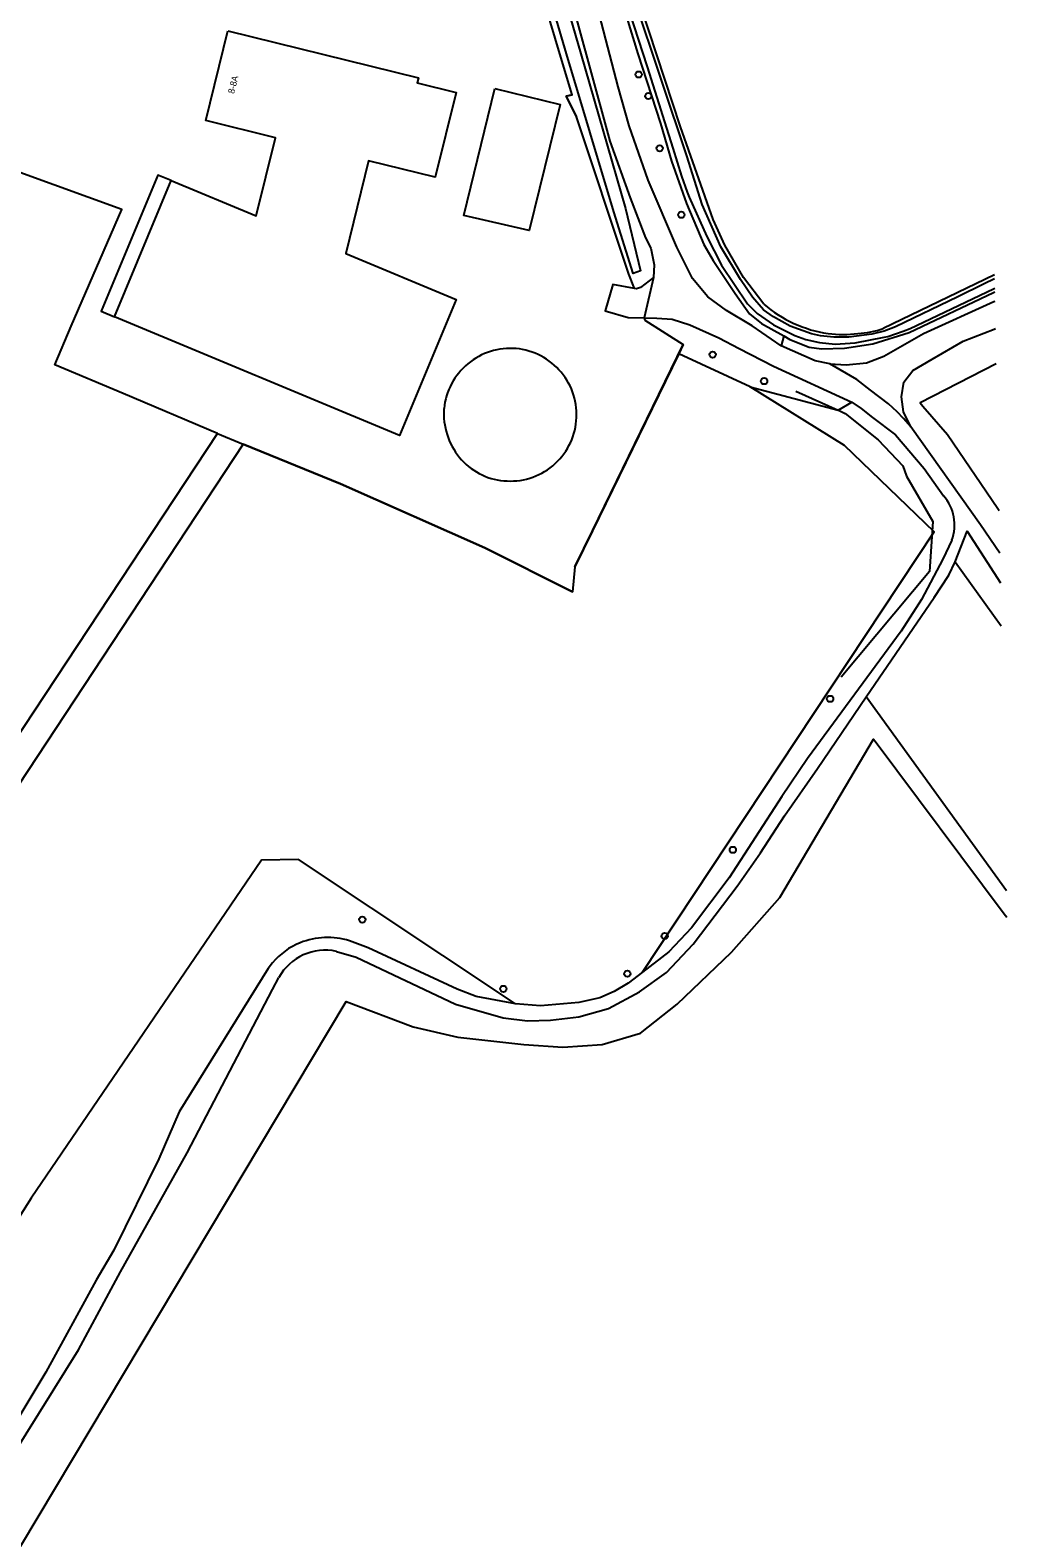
# Model space of a CAD drawing. Extents: x 163863 to 164644, y 379566 to 382155.
# Drawn here: x 164462.3 to 164614.2, y 381019.3 to 381253.7 of the extents above; entities that cross this region are included whole.
import ezdxf

# ---------------------------------------------------------------- set-up
doc = ezdxf.new("R2010")
doc.units = 0
for name, color, linetype in [('IMGEO_Berm_groen', 7, 'Continuous'), ('IMGEO_Boom', 7, 'Continuous'), ('IMGEO_Gemengd_bos', 7, 'Continuous'), ('IMGEO_Grasland_agrarisch', 7, 'Continuous'), ('IMGEO_Grasland_overig', 7, 'Continuous'), ('IMGEO_Groenvoorziening', 7, 'Continuous'), ('IMGEO_Hek', 7, 'Continuous'), ('IMGEO_Loofbos', 7, 'Continuous'), ('IMGEO_Open_loods', 7, 'Continuous'), ('IMGEO_Pand', 7, 'Continuous'), ('IMGEO_Pand_nummerreeks', 7, 'Continuous'), ('IMGEO_Pand_overbouw', 7, 'Continuous'), ('IMGEO_Rijbaan_lokaal_onverhard', 7, 'Continuous'), ('IMGEO_Rijbaan_lokaal_open', 7, 'Continuous'), ('IMGEO_Sloot', 7, 'Continuous'), ('IMGEO_Waterloop', 7, 'Continuous')]:
    doc.layers.add(name, color=color, linetype=linetype)

msp = doc.modelspace()

# ---------------------------------------------------------------- linework, layer by layer
at = {"layer": 'IMGEO_Berm_groen'}
for points in [[(164579.48, 381206.15), (164580.44, 381205.6), (164583.43, 381204.4), (164585.35, 381204.15), (164588.95, 381204.24), (164593.32, 381204.91), (164599.01, 381206.67), (164612.12, 381212.9), (164612.31, 381212.99)], [(164579.48, 381206.15), (164579.11, 381204.6)], [(164612.52, 381201.83), (164600.71, 381195.76), (164601.11, 381195.25), (164604.93, 381190.83), (164612.77, 381179.3), (164612.96, 381179.03)]]:
    msp.add_lwpolyline(points, dxfattribs=at)
at = {"layer": 'IMGEO_Boom'}
for centre in [(164556.92, 381246.81), (164558.42, 381243.45), (164560.21, 381235.34), (164563.56, 381224.99), (164568.43, 381203.25), (164576.44, 381199.13), (164586.7, 381149.73), (164571.57, 381126.25), (164513.95, 381115.39), (164560.97, 381112.84), (164555.18, 381106.99), (164535.89, 381104.63)]:
    msp.add_circle(centre, 0.489, dxfattribs=at)
at = {"layer": 'IMGEO_Gemengd_bos'}
for points in [[(164557.53, 381107.22), (164602.9, 381175.67), (164588.92, 381189.1), (164574.27, 381198.23)], [(164574.27, 381198.23), (164587.94, 381194.61), (164590.09, 381195.84)]]:
    msp.add_lwpolyline(points, dxfattribs=at)
at = {"layer": 'IMGEO_Grasland_agrarisch'}
for points in [[(164576.41, 381211.1), (164573.23, 381215.26), (164570.32, 381220.27), (164568.53, 381224.27), (164563.46, 381238.67), (164557.34, 381257.3), (164556.93, 381259.1), (164557.37, 381263.39), (164552.4, 381279.61), (164551.54, 381283.27), (164550.85, 381284.34), (164548.58, 381287.22), (164544.33, 381298.3), (164538.21, 381318.01), (164536.75, 381321.62), (164536.3, 381322.47)], [(164491.42, 381190.96), (164476.78, 381197.2), (164466.17, 381201.68), (164468.67, 381207.69), (164476.57, 381225.79), (164455.37, 381233.49), (164449.22, 381234.75), (164447.64, 381227.22), (164435.91, 381232.23), (164414.92, 381240.8), (164405.79, 381228.47)], [(164612.26, 381215.65), (164594.95, 381207.29)], [(164563.17, 381203.39), (164549.74, 381175.85), (164547, 381170.23), (164546.62, 381166.36), (164532.99, 381173.22), (164510.56, 381183.16), (164495.42, 381189.33)], [(164574.27, 381198.23), (164563.17, 381203.39)]]:
    msp.add_lwpolyline(points, dxfattribs=at)
for centre, radius, start, end in [((164589.43, 381226.31), 20.03, 229.4578, 261.2234), ((164588.66, 381224.46), 18.08, 262.7499, 277.4727), ((164590.23, 381221.16), 14.65, 273.04, 288.814)]:
    msp.add_arc(centre, radius, start, end, dxfattribs=at)
at = {"layer": 'IMGEO_Grasland_overig'}
for points in [[(164495.42, 381189.33), (164397.81, 381041.2), (164394.38, 381043.92), (164491.42, 381190.96)], [(164491.42, 381190.96), (164495.42, 381189.33)]]:
    msp.add_lwpolyline(points, dxfattribs=at)
at = {"layer": 'IMGEO_Groenvoorziening'}
for points in [[(164536.3, 381322.47), (164536.11, 381322.4), (164534.55, 381321.89), (164534.29, 381321.38), (164536.91, 381312.6), (164539.75, 381303.88), (164542.82, 381293.93), (164545.36, 381286.71), (164546.33, 381285.83), (164548.13, 381283.64), (164548.81, 381282.59), (164554.8, 381263.71), (164554.09, 381259.85), (164554.07, 381259.03), (164556.78, 381250.03), (164560.31, 381239.18), (164562.03, 381233.31), (164564.38, 381226.73), (164567.04, 381220.38), (164568.5, 381217.9), (164571.91, 381212.76), (164574.18, 381209.58), (164576.04, 381208.08), (164579.48, 381206.15)], [(164556.3, 381213.51), (164555.39, 381215.78), (164555.19, 381216.36), (164547.24, 381240.23), (164545.64, 381243.44), (164546.57, 381243.66), (164544.69, 381250), (164540.48, 381264.15), (164540.22, 381265.04), (164529.13, 381268.21), (164519.66, 381272.56), (164519.13, 381272.75)], [(164557.76, 381208.98), (164557.87, 381208.62), (164563.87, 381204.82), (164563.17, 381203.39)]]:
    msp.add_lwpolyline(points, dxfattribs=at)
at = {"layer": 'IMGEO_Hek'}
for points in [[(164546.57, 381243.66), (164545.64, 381243.44), (164547.24, 381240.23)], [(164468.67, 381207.69), (164476.57, 381225.79), (164455.37, 381233.49), (164449.22, 381234.75)], [(164491.42, 381190.96), (164476.78, 381197.2), (164466.17, 381201.68), (164468.67, 381207.69)], [(164547, 381170.23), (164549.74, 381175.85), (164563.87, 381204.82)], [(164581.36, 381197.59), (164587.94, 381194.61)], [(164587.94, 381194.61), (164588.1, 381194.54)], [(164588.1, 381194.54), (164589.05, 381194.1), (164594.17, 381190.01), (164597.98, 381185.97), (164598.57, 381184.37), (164602.69, 381177.28), (164602.15, 381169.55), (164588.41, 381153.12)], [(164495.42, 381189.33), (164397.81, 381041.2), (164394.38, 381043.92), (164491.42, 381190.96)], [(164491.42, 381190.96), (164495.42, 381189.33)], [(164495.42, 381189.33), (164510.56, 381183.16), (164532.99, 381173.22), (164546.62, 381166.36)]]:
    msp.add_lwpolyline(points, dxfattribs=at)
at = {"layer": 'IMGEO_Loofbos'}
for points in [[(164606.14, 381171.03), (164613.31, 381161.07)], [(164614.1, 381119.89), (164592.33, 381150.04)], [(164459.78, 380894.18), (164434.24, 380899.21), (164433.15, 380965.61), (164434.34, 380973.7), (164511.44, 381102.66), (164521.89, 381098.72), (164528.79, 381097.14), (164539.05, 381095.96), (164545.16, 381095.56), (164551.27, 381095.96), (164557.19, 381097.73), (164562.91, 381102.27), (164571.39, 381110.35), (164578.88, 381118.83), (164593.47, 381143.48), (164593.71, 381143.13), (164613.76, 381116.31), (164614.18, 381115.76)], [(164537.77, 381102.28), (164504.04, 381124.74), (164498.31, 381124.65), (164462.45, 381072.06), (164450.08, 381052.56), (164433.46, 381023.94), (164416.65, 380993.03), (164417.52, 380979.9)]]:
    msp.add_lwpolyline(points, dxfattribs=at)
at = {"layer": 'IMGEO_Open_loods'}
for centre, radius, start, end in [((164537.02, 381193.77), 10.45, 85.2742, 129.4704), ((164536.91, 381193.84), 10.39, 39.9242, 84.6782), ((164537.04, 381193.81), 10.43, 129.7074, 174.2176), ((164537.07, 381193.95), 10.2, 354.472, 40.0119), ((164537.55, 381194.13), 10.92, 176.1353, 218.8855), ((164537, 381193.87), 10.27, 309.7584, 354.9208), ((164536.78, 381193.59), 9.98, 219.2706, 265.2458), ((164537, 381193.79), 10.2, 264.0995, 310.0286)]:
    msp.add_arc(centre, radius, start, end, dxfattribs=at)
at = {"layer": 'IMGEO_Pand'}
for points in [[(164493.07, 381253.59), (164522.69, 381246.3), (164522.5, 381245.5), (164528.55, 381244.02), (164525.29, 381230.84), (164514.94, 381233.36), (164511.38, 381218.98), (164528.53, 381211.84), (164519.74, 381190.67), (164475.41, 381209.15), (164484.22, 381230.3), (164497.43, 381224.83), (164500.46, 381236.94), (164489.62, 381239.63), (164493.07, 381253.59)], [(164534.59, 381244.64), (164544.74, 381242.15), (164539.92, 381222.53), (164529.75, 381224.89), (164534.59, 381244.64)]]:
    msp.add_lwpolyline(points, dxfattribs=at)
at = {"layer": 'IMGEO_Pand_overbouw'}
msp.add_lwpolyline([(164484.22, 381230.3), (164482.19, 381231.14), (164473.38, 381210), (164475.41, 381209.15)], close=True, dxfattribs=at)
at = {"layer": 'IMGEO_Rijbaan_lokaal_onverhard'}
for points in [[(164474.21, 381290.55), (164483.96, 381287.46), (164498.67, 381282.49), (164519.5, 381276.01), (164529.34, 381273.18), (164538.66, 381270.43), (164541.43, 381268.75), (164543.02, 381266.93), (164544.34, 381264.96), (164545.66, 381261.33), (164549.08, 381248.8), (164552.47, 381236.46), (164555.63, 381227.65), (164557.99, 381221.41), (164558.81, 381219.82), (164559.36, 381217.23), (164559.22, 381215.24)], [(164579.11, 381204.6), (164574.56, 381207.73), (164570.59, 381210.11), (164567.68, 381212.22), (164565.32, 381215.07), (164562.87, 381219.96), (164558.43, 381230.39), (164555.47, 381238.84), (164553.72, 381244.89), (164550.85, 381256.01), (164547.6, 381267.91), (164544.02, 381275.23)], [(164586.65, 381201.83), (164589.18, 381201.68), (164592.36, 381201.97), (164595.03, 381203.03), (164601.2, 381206.54), (164612.15, 381211.51), (164612.34, 381211.58)], [(164557.76, 381208.98), (164559.78, 381208.94), (164562.14, 381208.75), (164564.89, 381207.88), (164569.39, 381205.84), (164572.58, 381204.2), (164577.91, 381201.43), (164590.09, 381195.84)], [(164599.24, 381192.03), (164598.11, 381194.37), (164597.81, 381196.68), (164598.14, 381198.98), (164599.56, 381200.8), (164602.57, 381202.55), (164607.37, 381205.34), (164612.23, 381207.21), (164612.42, 381207.3)], [(164586.65, 381201.83), (164584.36, 381202.3), (164579.11, 381204.6)], [(164599.24, 381192.03), (164598.13, 381193.31), (164597.11, 381194.38), (164595.79, 381195.61), (164593, 381197.74), (164590.86, 381199.36), (164586.65, 381201.83)], [(164590.09, 381195.84), (164591.51, 381194.86), (164593.3, 381193.47), (164596.85, 381190.77), (164601.31, 381185.54), (164604.35, 381181.3)], [(164613.09, 381172.4), (164610.08, 381176.78), (164599.24, 381192.03)], [(164606.14, 381171.03), (164607.99, 381175.81), (164613.18, 381167.75)], [(164605.64, 381174.38), (164604.2, 381171.47), (164600.92, 381165.15), (164597.75, 381160.27), (164583.18, 381140.44), (164579.18, 381134.54), (164571.02, 381121.89), (164565.12, 381114.11), (164561.61, 381110.39), (164557.53, 381107.22)], [(164592.33, 381150.04), (164602.88, 381165.5), (164605.16, 381168.97), (164606.14, 381171.03)], [(164509.94, 381110.46), (164513, 381109.56), (164528.45, 381102.23), (164535.88, 381100.11), (164539.67, 381099.67), (164543.21, 381099.75), (164547.64, 381100.28), (164552.22, 381101.59), (164557.08, 381104.16), (164561.26, 381107.19), (164565.4, 381111.59), (164572.27, 381120.6), (164575.89, 381125.77), (164579.6, 381131.54), (164584.73, 381138.89), (164592.33, 381150.04)], [(164537.77, 381102.28), (164531.66, 381103.46), (164528.71, 381104.56), (164514.89, 381111.01), (164511.96, 381112.11)], [(164500, 381108.67), (164499.33, 381107.79), (164485.48, 381085.49), (164482.32, 381078.21), (164475.33, 381063.99), (164472.56, 381059.31), (164464.73, 381045.03), (164457.76, 381033.36), (164451.17, 381024.3), (164449.47, 381021.73), (164448.22, 381019.51), (164443.56, 381010.28), (164437.71, 381000), (164430.52, 380987.39), (164427.27, 380980.74)], [(164557.53, 381107.22), (164555.31, 381105.49), (164553.14, 381104.2), (164550.89, 381103.22), (164547.61, 381102.5), (164541.67, 381102), (164537.77, 381102.28)], [(164430.23, 380982.04), (164433.13, 380988.18), (164439.99, 381000), (164451.52, 381019.23), (164469.81, 381048.48), (164476.37, 381060.64), (164486.72, 381079.14), (164500, 381104.54), (164500.97, 381106.4)]]:
    msp.add_lwpolyline(points, dxfattribs=at)
for centre, radius, start, end in [((164599.17, 381176.75), 6.89, 339.9252, 41.3342), ((164508.34, 381101.72), 10.86, 111.8485, 140.1745), ((164508.57, 381101.12), 11.5, 72.8645, 111.8003), ((164508.22, 381102.31), 8.33, 78.1113, 150.583)]:
    msp.add_arc(centre, radius, start, end, dxfattribs=at)
at = {"layer": 'IMGEO_Rijbaan_lokaal_open'}
for points in [[(164559.22, 381215.24), (164557.24, 381213.71), (164556.58, 381213.46), (164556.3, 381213.51)], [(164559.22, 381215.24), (164557.76, 381208.98)], [(164556.3, 381213.51), (164552.9, 381214.15), (164551.74, 381210.06), (164555.31, 381209.02), (164557.76, 381208.98)]]:
    msp.add_lwpolyline(points, dxfattribs=at)
at = {"layer": 'IMGEO_Sloot'}
for points in [[(164554.85, 381258.56), (164558.24, 381248), (164560.95, 381239.43), (164562.23, 381235.35), (164563.59, 381231.01), (164564.48, 381228.53), (164564.76, 381227.74), (164567.53, 381221.61), (164569.82, 381217.16), (164573.86, 381211.15), (164575.36, 381209.65), (164577.88, 381207.87), (164581.23, 381206.22), (164582.94, 381205.6), (164585.04, 381205.16), (164587.47, 381204.89), (164590.58, 381205.08), (164595.1, 381205.99), (164595.65, 381206.09), (164598.04, 381206.92), (164599.14, 381207.33), (164612.11, 381213.48), (164612.3, 381213.56)], [(164612.27, 381215.01), (164610.67, 381214.26), (164606.54, 381212.23), (164596.87, 381207.55), (164595.11, 381206.92), (164593.16, 381206.43), (164589.63, 381205.99), (164587.3, 381205.94), (164585.2, 381206.16), (164583.79, 381206.47), (164580.5, 381207.67), (164577.91, 381209.11), (164576.33, 381210.2), (164574.61, 381212.18), (164572.74, 381214.93), (164569.72, 381220.02), (164566.79, 381226.61), (164564.44, 381234.15), (164560.56, 381245.59), (164556.08, 381259.13)]]:
    msp.add_lwpolyline(points, dxfattribs=at)
at = {"layer": 'IMGEO_Waterloop'}
for points in [[(164545.72, 381250), (164542.18, 381262.02)], [(164544.35, 381262.41), (164544.61, 381261.49), (164547.93, 381250), (164554.87, 381225.96), (164557.19, 381216.3), (164556.08, 381215.89), (164553.07, 381225.44), (164545.72, 381250)]]:
    msp.add_lwpolyline(points, dxfattribs=at)

# ---------------------------------------------------------------- texts
at = {"layer": 'IMGEO_Pand_nummerreeks'}
msp.add_text('8-8A', height=1, rotation=75.8883, dxfattribs=at).set_placement((164494.02, 381243.75))

doc.saveas('drawing.dxf')
